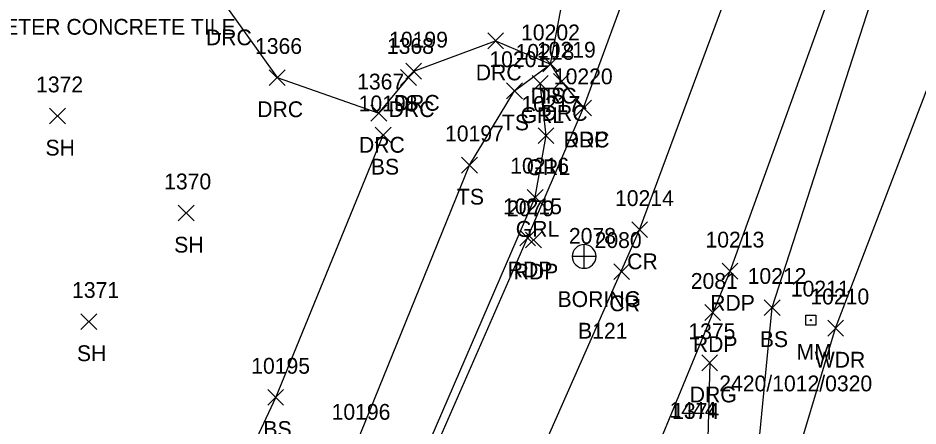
# Model space of a CAD drawing. Extents: x 1651685 to 1653558, y 889533 to 891085.
# Drawn here: x 1652677.7 to 1652791.5, y 890337.8 to 890389.4 of the extents above; entities that cross this region are included whole.
import ezdxf

# ---------------------------------------------------------------- set-up
doc = ezdxf.new("R2010")
doc.units = 0
for name, color, linetype in [('G_A', 7, 'Continuous'), ('G_C', 7, 'Continuous'), ('G_I', 7, 'Continuous'), ('GA_P', 7, 'Continuous'), ('L_A', 7, 'Continuous'), ('L_I', 7, 'Continuous'), ('L_TIC', 7, 'Continuous'), ('LAWA', 7, 'Continuous'), ('LELB', 7, 'Continuous'), ('P_A', 7, 'Continuous'), ('P_I', 7, 'Continuous'), ('P_TIC', 7, 'Continuous'), ('PET', 7, 'Continuous'), ('PRC', 7, 'Continuous'), ('R_A', 7, 'Continuous'), ('R_I', 7, 'Continuous'), ('R_TIC', 7, 'Continuous'), ('RDG', 7, 'Continuous'), ('RDP', 7, 'Continuous'), ('RGR', 7, 'Continuous'), ('S_A', 7, 'Continuous'), ('S_C', 7, 'Continuous'), ('S_I', 7, 'Continuous'), ('SRM', 7, 'Continuous'), ('U_C', 7, 'Continuous'), ('U_I', 7, 'Continuous')]:
    doc.layers.add(name, color=color, linetype=linetype)

msp = doc.modelspace()

# ---------------------------------------------------------------- linework, layer by layer
at = {"layer": 'GA_P'}
for p, q in [((1652749.28, 890359.22), (1652749.28, 890360.72)), ((1652749.28, 890359.22), (1652747.78, 890359.22)), ((1652750.78, 890359.22), (1652749.28, 890359.22)), ((1652749.28, 890357.72), (1652749.28, 890359.22))]:
    msp.add_line(p, q, dxfattribs=at)
for start, end in [(90, 180), (0, 90), (180, 270), (270, 0)]:
    msp.add_arc((1652749.28, 890359.22), 1.5, start, end, dxfattribs=at)
at = {"layer": 'L_TIC'}
for points in [[(1652744.04, 890382.57), (1652746.04, 890384.57)], [(1652746.04, 890382.57), (1652744.04, 890384.57)], [(1652739.48, 890379.18), (1652741.48, 890381.18)], [(1652741.48, 890379.18), (1652739.48, 890381.18)], [(1652681.69, 890375.99), (1652683.69, 890377.99)], [(1652683.69, 890375.99), (1652681.69, 890377.99)], [(1652722.87, 890373.58), (1652724.87, 890375.58)], [(1652724.87, 890373.58), (1652722.87, 890375.58)], [(1652733.79, 890369.78), (1652735.79, 890371.78)], [(1652735.79, 890369.78), (1652733.79, 890371.78)], [(1652697.96, 890363.71), (1652699.96, 890365.71)], [(1652699.96, 890363.71), (1652697.96, 890365.71)], [(1652772.05, 890351.75), (1652774.05, 890353.75)], [(1652774.05, 890351.75), (1652772.05, 890353.75)], [(1652685.67, 890349.97), (1652687.67, 890351.97)], [(1652687.67, 890349.97), (1652685.67, 890351.97)], [(1652780.07, 890349.15), (1652782.07, 890351.15)], [(1652782.07, 890349.15), (1652780.07, 890351.15)], [(1652709.29, 890340.38), (1652711.29, 890342.38)], [(1652711.29, 890340.38), (1652709.29, 890342.38)]]:
    msp.add_lwpolyline(points, dxfattribs=at)
at = {"layer": 'LAWA'}
msp.add_lwpolyline([(1652733.24, 890255.05), (1652739.87, 890255.53), (1652757.33, 890267.07), (1652768.84, 890309.36), (1652781.07, 890350.15), (1652797.71, 890393.69), (1652815.71, 890436.04), (1652825.05, 890456.62), (1652833.35, 890477.68), (1652833.39, 890492.3)], dxfattribs=at)
at = {"layer": 'LELB'}
for points in [[(1652703.44, 890293.38), (1652705.14, 890306.53), (1652720.51, 890335.55), (1652734.79, 890370.78), (1652740.48, 890380.18), (1652745.04, 890383.57), (1652748.86, 890403.84), (1652752.07, 890412.25), (1652759.38, 890425.62), (1652765.14, 890443.5), (1652773.03, 890464.56), (1652787.9, 890509.35)], [(1652768.84, 890309.36), (1652773.05, 890352.75), (1652787.7, 890398.23), (1652803.19, 890441), (1652820.95, 890497.33)], [(1652702.45, 890324.57), (1652710.29, 890341.38), (1652723.87, 890374.58)]]:
    msp.add_lwpolyline(points, dxfattribs=at)
at = {"layer": 'P_TIC'}
for points in [[(1652748.2, 890377.01), (1652750.2, 890379.01)], [(1652750.2, 890377.01), (1652748.2, 890379.01)], [(1652755.29, 890361.6), (1652757.29, 890363.6)], [(1652757.29, 890361.6), (1652755.29, 890363.6)], [(1652741.13, 890360.56), (1652743.13, 890362.56)], [(1652743.13, 890360.56), (1652741.13, 890362.56)], [(1652741.87, 890360.31), (1652743.87, 890362.31)], [(1652743.87, 890360.31), (1652741.87, 890362.31)], [(1652753.03, 890356.29), (1652755.03, 890358.29)], [(1652755.03, 890356.29), (1652753.03, 890358.29)], [(1652766.72, 890356.35), (1652768.72, 890358.35)], [(1652768.72, 890356.35), (1652766.72, 890358.35)], [(1652764.53, 890351.12), (1652766.53, 890353.12)], [(1652766.53, 890351.12), (1652764.53, 890353.12)]]:
    msp.add_lwpolyline(points, dxfattribs=at)
at = {"layer": 'PET'}
for points in [[(1652703.16, 890284.22), (1652712.82, 890300.53), (1652728.55, 890330.54), (1652742.13, 890361.56), (1652749.2, 890378.01), (1652759.76, 890406.83), (1652771.73, 890443.53), (1652776.68, 890458.63), (1652791.9, 890507.53)], [(1652703.16, 890284.22), (1652712.04, 890274.26), (1652722.33, 890261.92), (1652735.14, 890284.01), (1652751.62, 890318.12), (1652767.72, 890357.35), (1652783.18, 890400.14), (1652797.7, 890444.76), (1652815.98, 890499.36)]]:
    msp.add_lwpolyline(points, dxfattribs=at)
at = {"layer": 'PRC'}
msp.add_lwpolyline([(1652712.04, 890274.26), (1652722.86, 890292.98), (1652739.69, 890324.96), (1652756.29, 890362.6), (1652772.67, 890406.81), (1652786.21, 890448.94), (1652804.54, 890503.78)], dxfattribs=at)
at = {"layer": 'R_TIC'}
for points in [[(1652737.09, 890385.51), (1652739.09, 890387.51)], [(1652739.09, 890385.51), (1652737.09, 890387.51)], [(1652744.04, 890382.57), (1652746.04, 890384.57)], [(1652746.04, 890382.57), (1652744.04, 890384.57)], [(1652726.73, 890381.66), (1652728.73, 890383.66)], [(1652728.73, 890381.66), (1652726.73, 890383.66)], [(1652709.47, 890380.85), (1652711.47, 890382.85)], [(1652711.47, 890380.85), (1652709.47, 890382.85)], [(1652726.08, 890380.86), (1652728.08, 890382.86)], [(1652728.08, 890380.86), (1652726.08, 890382.86)], [(1652742.71, 890380.11), (1652744.71, 890382.11)], [(1652744.71, 890380.11), (1652742.71, 890382.11)], [(1652745.42, 890380.38), (1652747.42, 890382.38)], [(1652747.42, 890380.38), (1652745.42, 890382.38)], [(1652748.2, 890377.01), (1652750.2, 890379.01)], [(1652750.2, 890377.01), (1652748.2, 890379.01)], [(1652722.32, 890376.35), (1652724.32, 890378.35)], [(1652724.32, 890376.35), (1652722.32, 890378.35)], [(1652743.46, 890373.51), (1652745.46, 890375.51)], [(1652745.46, 890373.51), (1652743.46, 890375.51)], [(1652742.09, 890365.71), (1652744.09, 890367.71)], [(1652744.09, 890365.71), (1652742.09, 890367.71)], [(1652764.15, 890344.75), (1652766.15, 890346.75)], [(1652766.15, 890344.75), (1652764.15, 890346.75)]]:
    msp.add_lwpolyline(points, dxfattribs=at)
at = {"layer": 'RDG'}
msp.add_lwpolyline([(1652765.15, 890345.75), (1652764.72, 890328.25), (1652762.74, 890304.76), (1652758.96, 890277.3), (1652744.88, 890274.96), (1652728.28, 890271.77)], dxfattribs=at)
at = {"layer": 'RDP'}
for points in [[(1652732.88, 890405.28), (1652721.2, 890410.17), (1652696.73, 890422.63), (1652691.94, 890412.05), (1652708.98, 890400.51), (1652703.97, 890390.95), (1652710.47, 890381.85), (1652723.32, 890377.35), (1652727.08, 890381.86)], [(1652727.73, 890382.66), (1652738.09, 890386.51), (1652745.04, 890383.57), (1652746.42, 890381.38), (1652749.2, 890378.01)]]:
    msp.add_lwpolyline(points, dxfattribs=at)
at = {"layer": 'RGR'}
msp.add_lwpolyline([(1652703.79, 890286.45), (1652712.29, 890301.09), (1652727.67, 890331.01), (1652743.09, 890366.71), (1652744.46, 890374.51), (1652743.71, 890381.11)], dxfattribs=at)
at = {"layer": 'SRM'}
msp.add_lwpolyline([(1652777.32, 890351.77), (1652778.57, 890351.77), (1652778.57, 890350.52), (1652777.32, 890350.52)], close=True, dxfattribs=at)
msp.add_circle((1652777.94, 890351.15), 0.0833, dxfattribs=at)

# ---------------------------------------------------------------- texts
at = {"layer": 'G_A'}
msp.add_text('BORING', height=2, dxfattribs=at).set_placement((1652745.92, 890352.82))
at = {"layer": 'G_C'}
msp.add_text('B121', height=2, dxfattribs=at).set_placement((1652748.51, 890348.82))
at = {"layer": 'G_I'}
msp.add_text('2078', height=2, dxfattribs=at).set_placement((1652747.35, 890360.82))
at = {"layer": 'L_A'}
for s, p in [('TS', (1652743.45, 890378.57)), ('TS', (1652738.89, 890375.18)), ('SH', (1652681.18, 890371.99)), ('BS', (1652722.32, 890369.58)), ('TS', (1652733.2, 890365.78)), ('SH', (1652697.45, 890359.71)), ('BS', (1652771.49, 890347.75)), ('SH', (1652685.16, 890345.97)), ('WDR', (1652778.43, 890345.15)), ('BS', (1652708.73, 890336.38))]:
    msp.add_text(s, height=2, dxfattribs=at).set_placement(p)
at = {"layer": 'L_I'}
for s, p in [('10202', (1652741.3, 890386.57)), ('10201', (1652737.3, 890383.18)), ('1372', (1652679.99, 890379.99)), ('10198', (1652720.77, 890377.58)), ('10197', (1652731.69, 890373.78)), ('1370', (1652696.18, 890367.71)), ('10212', (1652769.95, 890355.75)), ('1371', (1652684.54, 890353.97)), ('10210', (1652777.88, 890353.15)), ('10195', (1652707.19, 890344.38)), ('10196', (1652717.35, 890338.55))]:
    msp.add_text(s, height=2, dxfattribs=at).set_placement(p)
at = {"layer": 'P_A'}
for s, p in [('RDP', (1652746.69, 890373.01)), ('CR', (1652754.72, 890357.6)), ('RDP', (1652739.62, 890356.56)), ('RDP', (1652740.36, 890356.31)), ('CR', (1652752.46, 890352.29)), ('RDP', (1652765.21, 890352.35)), ('RDP', (1652763.02, 890347.12))]:
    msp.add_text(s, height=2, dxfattribs=at).set_placement(p)
at = {"layer": 'P_I'}
for s, p in [('10220', (1652745.45, 890381.01)), ('10214', (1652753.18, 890365.6)), ('10215', (1652739.03, 890364.56)), ('2079', (1652739.53, 890364.31)), ('2080', (1652750.6, 890360.29)), ('10213', (1652764.62, 890360.35)), ('2081', (1652762.76, 890355.12))]:
    msp.add_text(s, height=2, dxfattribs=at).set_placement(p)
at = {"layer": 'R_A'}
for s, p in [('DRC', (1652701.46, 890385.95)), ('DRC', (1652735.58, 890381.51)), ('DRC', (1652725.22, 890377.66)), ('DRC', (1652742.53, 890378.57)), ('DRC', (1652707.95, 890376.85)), ('DRC', (1652724.57, 890376.86)), ('GRL', (1652741.25, 890376.11)), ('DRC', (1652743.91, 890376.38)), ('DRC', (1652720.81, 890372.35)), ('DRC', (1652746.69, 890373.01)), ('GRL', (1652742, 890369.51)), ('GRL', (1652740.63, 890361.71)), ('DRG', (1652762.63, 890340.75))]:
    msp.add_text(s, height=2, dxfattribs=at).set_placement(p)
at = {"layer": 'R_I'}
for s, p in [('10199', (1652724.62, 890385.66)), ('10202', (1652741.3, 890386.57)), ('1366', (1652707.67, 890384.85)), ('1368', (1652724.34, 890384.86)), ('10218', (1652740.6, 890384.11)), ('10219', (1652743.31, 890384.38)), ('1367', (1652720.58, 890380.35)), ('10220', (1652745.45, 890381.01)), ('10217', (1652741.35, 890377.51)), ('10216', (1652739.93, 890369.71)), ('1375', (1652762.45, 890348.75))]:
    msp.add_text(s, height=2, dxfattribs=at).set_placement(p)
at = {"layer": 'S_A'}
msp.add_text('MM', height=2, dxfattribs=at).set_placement((1652776.13, 890346.15))
at = {"layer": 'S_C'}
msp.add_text('2420/1012/0320', height=2, dxfattribs=at).set_placement((1652766.36, 890342.15))
at = {"layer": 'S_I'}
msp.add_text('10211', height=2, dxfattribs=at).set_placement((1652775.41, 890354.15))
at = {"layer": 'U_C'}
msp.add_text("3' DIAMETER CONCRETE TILE", height=2, dxfattribs=at).set_placement((1652666.52, 890387.28))
at = {"layer": 'U_I'}
for s, p in [('1444', (1652760.07, 890338.81)), ('1374', (1652760.4, 890338.66))]:
    msp.add_text(s, height=2, dxfattribs=at).set_placement(p)

doc.saveas('drawing.dxf')
